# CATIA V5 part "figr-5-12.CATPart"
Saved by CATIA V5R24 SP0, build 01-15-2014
Part number: Part1
Bounding box of the stored display mesh (mm): x 0 to 150, y -70 to 70, z -150 to 69.804
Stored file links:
  D:\KAVITA\CATIA V5-6R2014 Project_ Kavita\CATIA V5-6R2014_partfiles\Partfiles\c05_catia_v5-6r2014_prt\figr-5-12.CATPart
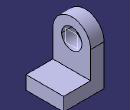
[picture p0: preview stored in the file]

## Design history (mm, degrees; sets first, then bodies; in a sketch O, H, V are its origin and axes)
Set1
  Plane1: type 1Curve, Element1 edge [face of Pad1 | face of Pad1]
Body1 (main body)
  Sketch1 on yz-plane, origin (0, 0, 0), H (0, 1, 0), V (0, 0, 1)
    arc A1 centre (0, 0) radius 70 from (70, 0) to (-70, 0) ccw
    point P1 (70, 0)
    point P2 (-70, 0)
    line L1 (-70, 0) -> (-70, -150)
    line L2 (-70, -150) -> (70, -150)
    line L3 (70, -150) -> (70, 0)
    circle A2 centre (0, 0) radius 37.5
    radius A1 = 70
    radius A2 = 37.5
    distance O L2 = 150
    coincidence: P1 H, P2 H
    tangency: L1 A1, L3 A1
    horizontal: L2 H
  Pad1: profile Sketch1, direction (1, 0, 0), length 50
  Sketch2 on face of Pad1, origin (50, 0, 0), H (0, 1, 0), V (0, 0, 1)
    line L1 (-70, -150) -> (70, -150)
    line L2 (70, -150) -> (70, -100)
    line L3 (70, -100) -> (-70, -100)
    line L4 (-70, -100) -> (-70, -150)
    reference projected line E1 (-70, -150) -> (70, -150) from edge [face of Pad1 | face of Pad1]
    reference projected line E2 (-70, 0) -> (-70, -150) from edge [face of Pad1 | face of Pad1]
    reference projected line E3 (70, -150) -> (70, 0) from edge [face of Pad1 | face of Pad1]
    length L2 = 50
    horizontal: L1 H, L3 H
    vertical: L2 V, L4 V
    coincidence: L1 E1, E2 L4, L2 E3
  Pad2: profile Sketch2, direction (1, 0, 0), length 100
